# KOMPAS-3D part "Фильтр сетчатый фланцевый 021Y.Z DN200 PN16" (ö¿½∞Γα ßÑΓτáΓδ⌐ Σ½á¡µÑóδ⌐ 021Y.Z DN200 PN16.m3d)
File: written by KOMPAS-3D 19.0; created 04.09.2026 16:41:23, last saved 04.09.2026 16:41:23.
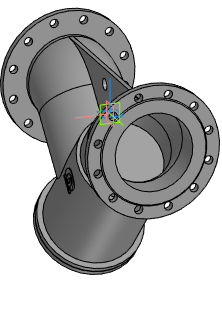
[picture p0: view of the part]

Document properties: Автор: Энергия; Полное имя файла: Z:\3.Личные\sachek\Dendor\_3D для проектировщиков\8.1 Фильтр сетчатый 021Y.Z\021Y.Z_STP\Фильтр сетчатый фланцевый 021Y.Z DN200 PN16.m3d

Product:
- Part/product: Фильтр сетчатый фланцевый 021Y.Z DN200 PN16

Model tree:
1. Операция без истории:1  (labels: Фильтр сетчатый фланцевый 021Y.Z DN200 PN16)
